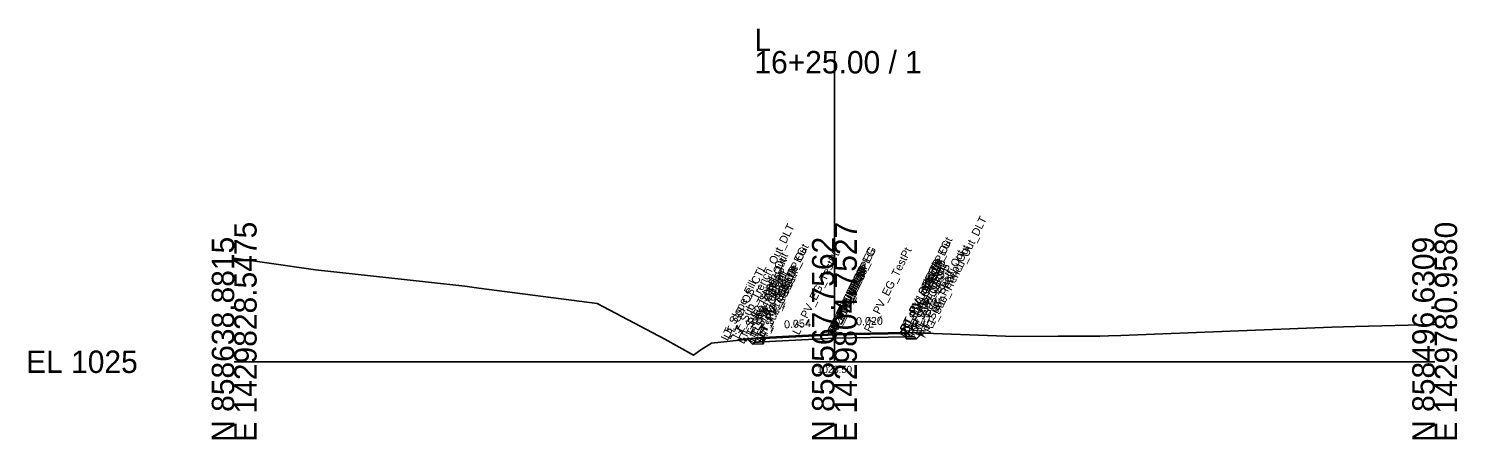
# Model space of a CAD drawing. Extents: x -26 to 153, y -10 to 13058.
# Drawn here: x -25.7 to 152.8, y 9490.3 to 9541.6 of the extents above; entities that cross this region are included whole.
import ezdxf

# ---------------------------------------------------------------- set-up
doc = ezdxf.new("R2010")
doc.units = 0
for name, color, linetype in [('Default', 7, 'Continuous'), ('Exist Cross Section Cell', 7, 'Continuous'), ('Exist XS Center Line Elevation Label', 7, 'Continuous'), ('Exist XS Ground Line', 7, 'Continuous'), ('Prop CMT Pvmt Course 1', 7, 'Continuous'), ('Prop CMT Pvmt Course 2', 7, 'Continuous'), ('Prop CMT Pvmt Surface', 7, 'Continuous'), ('Prop CMT Pvmt Surface Shoulder', 7, 'Continuous'), ('Prop CMT Pvmt Wedge Surface 1', 7, 'Continuous'), ('Prop CMT Pvmt Wedge Surface 2', 7, 'Continuous'), ('Prop CMT Shld Paved Course 1', 7, 'Continuous'), ('Prop CMT Shld Paved Course 2', 7, 'Continuous'), ('Prop CMT Slope Grass', 7, 'Continuous'), ('Prop CMT Subgrade Earthwork', 7, 'Continuous'), ('Prop XS Dump Level', 7, 'Continuous'), ('Prop XS SE Text', 7, 'Continuous'), ('Prop XS Side Slope Text', 7, 'Continuous')]:
    doc.layers.add(name, color=color, linetype=linetype)

msp = doc.modelspace()

# ---------------------------------------------------------------- linework, layer by layer
at = {"layer": 'Exist Cross Section Cell'}
for p, q in [((75, 9500), (75, 9538.8)), ((0, 9500), (75, 9500)), ((75, 9500), (150, 9500))]:
    msp.add_line(p, q, dxfattribs=at)
at = {"layer": 'Exist XS Ground Line'}
msp.add_lwpolyline([(0, 9512.93), (4.35, 9512.29), (10.14, 9511.47), (24.29, 9509.92), (28.8, 9509.45), (30.55, 9509.21), (45.36, 9507.29), (53.8, 9502.82), (57.37, 9500.84), (58.29, 9501.48), (59.65, 9502.32), (65.47, 9502.95), (66.08, 9503.02), (66.51, 9503.04), (74.92, 9503.49), (79.94, 9503.59), (84.01, 9503.67), (97.48, 9503.15), (102.94, 9503.18), (108.14, 9503.2), (109.24, 9503.22), (110.78, 9503.29), (124.43, 9503.83), (137.15, 9504.31), (140.05, 9504.4), (150, 9504.65)], dxfattribs=at)
at = {"layer": 'Prop CMT Pvmt Course 1'}
for points in [[(75, 9503.5), (66.05, 9503.01)], [(66.14, 9502.89), (75, 9503.37)], [(75, 9503.5), (83.95, 9503.67)], [(83.95, 9503.55), (75, 9503.37)], [(75, 9502.95), (75, 9503.5)], [(75, 9502.95), (75, 9503.5)], [(75, 9503.37), (75, 9502.95), (75, 9502.95)], [(75, 9503.37), (75, 9502.95), (75, 9502.95)], [(83.95, 9503.67), (83.95, 9503.13), (83.95, 9503.13), (83.95, 9503.55)], [(66.05, 9503.01), (66.05, 9502.47)], [(66.05, 9502.47), (66.14, 9502.48)], [(66.14, 9502.48), (66.14, 9502.89)]]:
    msp.add_lwpolyline(points, dxfattribs=at)
at = {"layer": 'Prop CMT Pvmt Course 2'}
for points in [[(66.14, 9502.48), (66.05, 9502.47)], [(66.05, 9502.47), (66.05, 9502.22)], [(66.05, 9502.22), (66.14, 9502.23)], [(66.14, 9502.23), (66.14, 9502.48)], [(83.95, 9502.88), (83.95, 9502.88), (83.95, 9503.13), (83.95, 9503.13)], [(83.95, 9503.13), (83.95, 9502.88)]]:
    msp.add_lwpolyline(points, dxfattribs=at)
at = {"layer": 'Prop CMT Pvmt Surface'}
for points in [[(75, 9503.5), (66.05, 9503.01)], [(75, 9503.5), (83.95, 9503.67)]]:
    msp.add_lwpolyline(points, dxfattribs=at)
at = {"layer": 'Prop CMT Pvmt Surface Shoulder'}
for points in [[(83.95, 9503.67), (83.95, 9503.67)], [(66.05, 9503.01), (66.05, 9503.01)]]:
    msp.add_lwpolyline(points, dxfattribs=at)
at = {"layer": 'Prop CMT Pvmt Wedge Surface 1'}
for points in [[(75, 9503.37), (66.14, 9502.89)], [(75, 9503.37), (83.95, 9503.55)], [(75, 9503.5), (75, 9502.95), (75, 9502.95), (75, 9503.37)], [(75, 9503.5), (75, 9502.95), (75, 9502.95), (75, 9503.37)], [(83.95, 9503.13), (83.95, 9503.67)], [(83.95, 9503.55), (83.95, 9503.13), (83.95, 9503.13)], [(66.05, 9502.47), (66.05, 9503.01)], [(66.14, 9502.48), (66.05, 9502.47)], [(66.14, 9502.89), (66.14, 9502.48)]]:
    msp.add_lwpolyline(points, dxfattribs=at)
at = {"layer": 'Prop CMT Pvmt Wedge Surface 2'}
for points in [[(75, 9503.5), (75, 9502.95)], [(75, 9503.5), (75, 9502.95)], [(83.95, 9503.13), (83.95, 9503.67)], [(66.05, 9502.47), (66.05, 9503.01)], [(75, 9502.95), (66.05, 9502.47)], [(75, 9502.95), (83.95, 9503.13)]]:
    msp.add_lwpolyline(points, dxfattribs=at)
at = {"layer": 'Prop CMT Shld Paved Course 1'}
for points in [[(83.95, 9503.67), (83.95, 9503.67)], [(83.95, 9503.67), (84.5, 9503.12)], [(83.95, 9503.13), (83.95, 9503.67)], [(66.05, 9503.01), (65.5, 9502.46)], [(65.5, 9502.46), (66.05, 9502.47)], [(66.05, 9503.01), (66.05, 9503.01)], [(66.05, 9502.47), (66.05, 9503.01)], [(84.5, 9503.12), (83.95, 9503.13)]]:
    msp.add_lwpolyline(points, dxfattribs=at)
at = {"layer": 'Prop CMT Shld Paved Course 2'}
for points in [[(66.05, 9502.47), (65.5, 9502.46), (65, 9502.45), (64.74, 9502.19)], [(64.74, 9502.19), (66.05, 9502.22)], [(66.05, 9502.22), (66.05, 9502.47)], [(83.95, 9503.13), (84.5, 9503.12), (85, 9503.11), (85.26, 9502.86)], [(83.95, 9502.88), (83.95, 9503.13)], [(85.26, 9502.86), (83.95, 9502.88)]]:
    msp.add_lwpolyline(points, dxfattribs=at)
at = {"layer": 'Prop CMT Slope Grass'}
for points in [[(83.95, 9503.67), (86.95, 9503.56)], [(66.05, 9503.01), (63.05, 9502.77), (62.84, 9502.67)]]:
    msp.add_lwpolyline(points, dxfattribs=at)
at = {"layer": 'Prop CMT Subgrade Earthwork'}
for points in [[(83.95, 9502.88), (83.94, 9503.67)], [(85.26, 9502.86), (86, 9503.6)], [(64.74, 9502.19), (64.08, 9502.85)], [(66.05, 9502.22), (64.74, 9502.19)], [(66.14, 9502.23), (66.05, 9502.22)], [(66.14, 9502.23), (66.16, 9503.02)], [(83.95, 9502.88), (83.95, 9502.88)], [(83.95, 9502.88), (85.26, 9502.86)]]:
    msp.add_lwpolyline(points, dxfattribs=at)

# ---------------------------------------------------------------- texts
at = {"layer": 'Default'}
msp.add_text('-', height=0.0001, dxfattribs=at).set_placement((0, 9500))
at = {"layer": 'Exist Cross Section Cell'}
for s, p in [('L', (65, 9538.8)), ('16+25.00 / 1', (65, 9536)), ('EL 1025', (-26, 9498.6))]:
    msp.add_text(s, height=2.8, dxfattribs=at).set_placement(p)
for s, p in [('E 1429828.5475', (2.8, 9490)), ('E 1429804.7527', (77.8, 9490)), ('E 1429780.9580', (152.8, 9490)), ('N 858638.8815', (0, 9490)), ('N 858567.7562', (75, 9490)), ('N 858496.6309', (150, 9490))]:
    msp.add_text(s, height=2.8, rotation=90, dxfattribs=at).set_placement(p)
at = {"layer": 'Exist XS Center Line Elevation Label'}
msp.add_text('1028.50', height=0.9, dxfattribs=at).set_placement((72.85, 9498.6))
msp.add_text('1028.50', height=0.9, dxfattribs=at).set_placement((72.85, 9498.6))
msp.add_text('1028.50', height=0.9, dxfattribs=at).set_placement((72.85, 9498.6))
at = {"layer": 'Prop XS Dump Level'}
for s, p in [('RT_Sub_Trench_Out_DLT', (86.97, 9503.54)), ('LT_Sub_Trench_Out_DLT', (63.03, 9502.8)), ('LT_PV_OEEOP_EG', (66.14, 9503.02)), ('LT_PV_Sub_Tie_Out', (66.16, 9503.02)), ('RT_PV_IEEOP_EG', (75, 9503.5)), ('LT_PV_IEEOP_EG', (75, 9503.5)), ('RT_PV_EG_TestPt', (79.52, 9503.59)), ('RT_PV_Sub_Tie_Out', (84.02, 9503.67)), ('RT_PV_OEEOP_EG', (84.03, 9503.67)), ('RT_Sub_Trench_Out', (86.31, 9502.88)), ('LT_Sub_Trench_Out', (63.69, 9502.14)), ('LT_PS2_Shelf_Out', (63.95, 9502.39)), ('LT_PV1_OEEOP', (66.14, 9502.89)), ('LT_PV_EG_TestPt', (70.57, 9503.26)), ('RT_PV1_IEEOP', (75, 9503.37)), ('LT_PV1_IEEOP', (75, 9503.37)), ('RT_PV1_OEEOP', (84.03, 9503.55)), ('RT_PV2_OEEOP', (84.03, 9503.14)), ('RT_Sub_OEEOP', (84.03, 9502.89)), ('RT_PV1_OEOT', (85, 9503.7)), ('RT_PS1_OEOP', (85, 9503.7)), ('RT_PS2_Shelf_Out', (86.05, 9503.13)), ('LT_GS_OS_CTL', (62, 9502.72)), ('LT_PS2_OEOP', (64.45, 9502.4)), ('LT_PV1_OEOT', (65, 9502.96)), ('LT_PS1_OEOP', (65, 9502.96)), ('LT_PV2_OEOT', (65, 9502.42)), ('LT_Sub_OEOT', (65, 9502.17)), ('LT_PV2_OEEOP', (66.14, 9502.48)), ('LT_Sub_OEEOP', (66.14, 9502.23)), ('RT_PV2_IEEOP', (75, 9502.96)), ('LT_PV2_IEEOP', (75, 9502.96)), ('RT_PV2_OEOT', (85, 9503.16)), ('RT_Sub_OEOT', (85, 9502.91)), ('RT_PS2_OEOP', (85.55, 9503.14)), ('LT_Slope_Fill', (61.64, 9502.54)), ('PV1_PGL', (75, 9503.5)), ('PV2_PGL', (75, 9502.96))]:
    msp.add_text(s, height=1, rotation=63.5833, dxfattribs=at).set_placement(p)
at = {"layer": 'Prop XS SE Text'}
for s, rotation, p in [('0.054', 3.091, (68.73, 9504.16)), ('0.020', 1.1458, (77.71, 9504.55))]:
    msp.add_text(s, height=1, rotation=rotation, dxfattribs=at).set_placement(p)
at = {"layer": 'Prop XS Side Slope Text'}
msp.add_text('2:1', height=1, rotation=26.5651, dxfattribs=at).set_placement((61.9, 9503.04))

doc.saveas('drawing.dxf')
